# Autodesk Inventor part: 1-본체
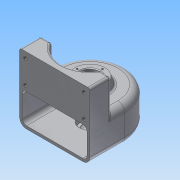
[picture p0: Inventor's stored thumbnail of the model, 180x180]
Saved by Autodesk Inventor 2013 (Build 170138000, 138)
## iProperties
Created: 2015-02
Part Number: 1-본체
Material: 알루미늄 6061
Document SubType Name: Modeling
Designer: Administrator
Density: 2.40731 g/cm^3
Mass: 511.027 g
Surface Area: 707.302 cm^2
Volume: 212.281 cm^3
Author: Administrator
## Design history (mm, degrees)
sketch "스케치1"
  geometry: L1 (-50, 0)-(-50, -50); L2 (-50, -50)-(50, -50); L3 (50, -50)-(50, 0); A1 r 50 centre (0, 0) between (-50, 0) and (50, 0); 1 further point
  constraints: 6 end point, 2 point on circle, 2 tangent, 1 centre point, 1 coincident, 1 parallel, 1 perpendicular, 1 vertical
  dimensions: "d0" = 50 radius of A1; "d2" = 50 distance from line of L2 point (0, 0)
extrude "돌출1" new body sketch "스케치1" distance "d3" = 50; taper "d4" = 0 deg
fillet "모깎기1" dims "d5" = 10
feature "쉘1" dims "d6" = 4
node "작업 평면1"
sketch "스케치3"
  geometry: L1 (-50, 0)-(-50, -50) reference; L2 (-40, -50)-(40, -50) reference; L3 (50, -50)-(50, 0) reference; L4 (50, -50)-(40, -50) reference; L5 (-40, -50)-(-50, -50) reference; L6 (34.641, -20)-(50, -20); L7 (-34.641, -20)-(-50, -20); L8 (-50, -20)-(-50, -50); L9 (-50, -50)-(50, -50); L10 (50, -50)-(50, -20); A1 r 40 centre (0, 0) between (-34.641, -20) and (34.641, -20); 1 further point
  constraints: 10 end point, 4 collinear, 2 point on circle, 2 point on line, 1 centre point, 1 coincident, 1 parallel
  dimensions: "d8" = 40 radius of A1; "d10" = 30 distance between parallel lines of L2 L6
extrude "돌출2" join sketch "스케치3" stored distance "d11" = 50; taper "d12" = 0 deg
sketch "스케치4"
  geometry: C1 r 25 at (0, 0); A1 r 40 centre (0, 0) between (-34.641, -20) and (34.641, -20) reference
  constraints: 1 centre point, 1 coincident
  dimensions: "d13" = 50 diameter of C1
extrude "돌출3" join sketch "스케치4" distance "d15" = 10; taper "d16" = -20 deg
sketch "스케치5"
  geometry: C1 r 20 at (0, 0); A1 r 40 centre (0, 0) between (40, 0) and (-40, 0) reference
  constraints: 1 centre point, 1 coincident
  dimensions: "d17" = 40 diameter of C1
extrude "돌출4" join sketch "스케치5" distance "d19" = 9; taper "d20" = 0 deg
hole "구멍1" diameter "d23" = 20; stored, may be unused: countersink angle "d27" = 90 deg, drill point angle "d29" = 0 deg; dims "d21" = 10, "d22" = 10, "d24" = 6, "d25" = 28, "d26" = 10, "d28" = 14
hole "구멍2" diameter "d32" = 20; stored, may be unused: countersink angle "d36" = 90 deg, drill point angle "d38" = 0 deg; dims "d30" = 10, "d31" = 10, "d33" = 6, "d34" = 28, "d35" = 8, "d37" = 10
sketch "스케치6"
  geometry: C1 r 14 at (0, 0) reference; C2 r 21.36 at (0, 0) reference; A1 r 18 centre (0, 0) between (0, 18) and (-18, 0); 2 further points
  constraints: 4 point on circle, 2 horizontal alignment, 2 vertical alignment, 1 centre point, 1 coincident
  dimensions: "d39" = 36 diameter of A1
hole "구멍3" sketch "스케치6" at (0, 18), (-18, 0), (18, 0), (0, -18) diameter "d41" = 2.459; stored, may be unused: countersink angle "d45" = 90 deg, drill point angle "d47" = 118 deg; dims "d42" = 6, "d43" = 28, "d44" = 8, "d46" = 9
sketch "스케치7"
  geometry: L1 (-10, 95)-(90, 95) reference; L2 (81.75, 53)-(-1.75, 53); L3 (-1.75, 53)-(-1.75, 86); L4 (-1.75, 86)-(81.75, 86); L5 (81.75, 86)-(81.75, 53); 7 further points
  constraints: 8 end point, 4 coincident, 2 midpoint, 2 parallel, 1 horizontal, 1 perpendicular, 1 vertical alignment
  dimensions: "d48" = 83.5 distance of L3.end L4.end; "d50" = 33 distance of L4.end L2.start; "d51" = 9 distance between parallel lines of L4 L1
hole "구멍4" sketch "스케치7" at (-1.75, 86), (81.75, 86), (81.75, 53), (-1.75, 53) diameter "d52" = 5.134; stored, may be unused: countersink angle "d56" = 90 deg, drill point angle "d58" = 118 deg; dims "d53" = 10, "d54" = 28, "d55" = 8, "d57" = 13
node "작업 평면2"
sketch "스케치8"
  geometry: L1 (40, 0)-(-40, 0) reference; 2 further points
  constraints: 1 vertical alignment, 1 other
  dimensions: "d59" = 25 distance from line of L1 point (0, 25)
feature "엠보싱1" sketch "스케치8" dims "d8" = 40, "d10" = 30, "d60" = 0.5, "d61" = 0
fillet "모깎기2" dims "d62" = 0.3
fillet "모깎기3" dims "d63" = 3
chamfer "모따기1" distance "d64" = 1; stored, may be unused: second distance "d65" = 2, angle "d66" = 45 deg
node "솔리드1"
other parameters: "d7" = -95
